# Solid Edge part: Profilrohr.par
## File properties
Username: ahadarics
Dokumentum tartalom típus: 0
Author: ahadarics
Last saved by: ahadarics
Revision: 78
Sűrűség: 0,000 kg/m^3
Pontosság: 0,990
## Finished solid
Body 1: solid body, 115 faces, 338 edges, 224 vertices.
  Faces by surface: cylinder 59, plane 56
  Edges by curve: line 220, circle 118
Bounding box of the edges (mm): 77.000 x 77.000 x 36.500, from (-38.5, -38.5, 0) to (38.5, 38.5, 36.5).
Cylindrical faces by radius (mm): R0.15 x24, R0.25 x24, R1 x4, R12 x4, R13.5 x2, R31.5 x1
Planar faces by outward normal: +x 13, +y 14, +z 1, -x 13, -y 14, -z 1
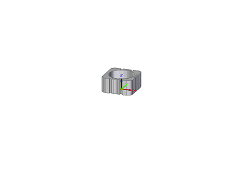
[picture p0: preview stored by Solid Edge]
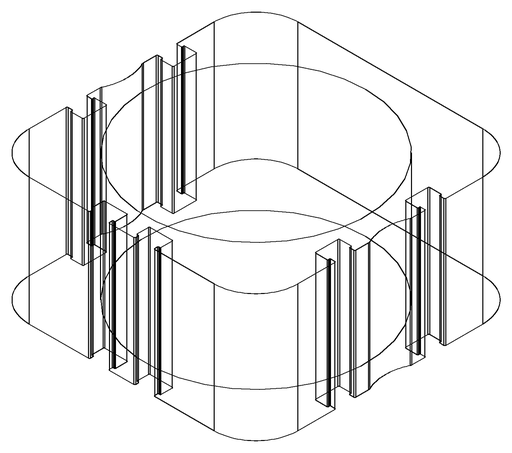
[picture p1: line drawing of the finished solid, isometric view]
